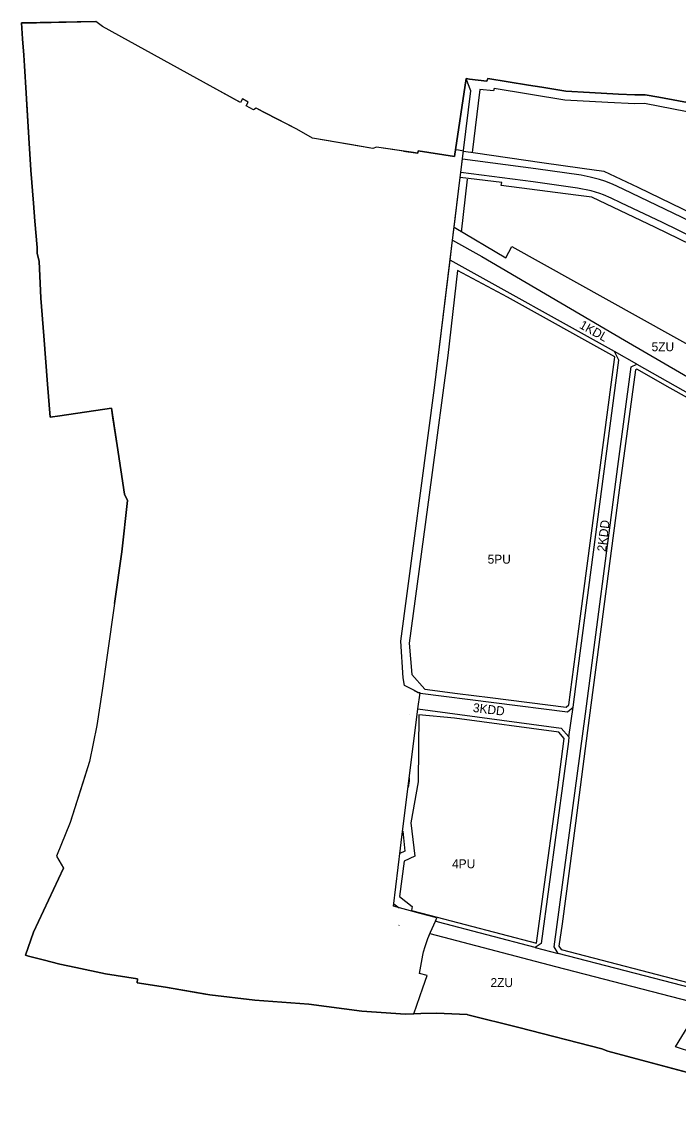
# Model space of a CAD drawing. Extents: x 7428203 to 7432868, y 5542672 to 5545406.
# Drawn here: x 7428203 to 7428940, y 5544072 to 5545281 of the extents above; entities that cross this region are included whole.
import ezdxf

# ---------------------------------------------------------------- set-up
doc = ezdxf.new("R2010")
doc.units = 0
for name, color, linetype in [('__LEGENDA_RAMKA_LOGO_PODZIAŁKA', 7, 'Continuous'), ('_GRANICA_MIASTA', 7, 'Continuous'), ('granicaBulwary', 7, 'Continuous'), ('LIN_Granica Planu', 7, 'Continuous'), ('MPZP_uchwalone_nieobowiazujace jeszcze_SZRAF', 7, 'Continuous')]:
    doc.layers.add(name, color=color, linetype=linetype)

msp = doc.modelspace()

# ---------------------------------------------------------------- linework, layer by layer
at = {"layer": '__LEGENDA_RAMKA_LOGO_PODZIAŁKA'}
msp.add_lwpolyline([(7428955.8, 5545189.3), (7428917.9, 5545196.3), (7428902.5, 5545199), (7428891, 5545198.8), (7428872.5, 5545199.5), (7428840.3, 5545201.4), (7428813.7, 5545202.9), (7428786.7, 5545207.3), (7428771.7, 5545209.8), (7428726, 5545217.2), (7428725.1, 5545214.2), (7428705.6, 5545216.5), (7428701.7, 5545217.3), (7428688.7, 5545129.6), (7428648, 5545136.2), (7428647.7, 5545133.5), (7428631.6, 5545135.8), (7428601.2, 5545140.2), (7428597.2, 5545138.9), (7428571.9, 5545143.2), (7428529.6, 5545150.4), (7428512, 5545160.3), (7428466.3, 5545184), (7428463.5, 5545182.1), (7428455.3, 5545186.6), (7428457.6, 5545190.8), (7428451.2, 5545194.3), (7428448.8, 5545190.4), (7428447.5, 5545191), (7428294.1, 5545275.5), (7428286.7, 5545281), (7428203.4, 5545279.4), (7428204.6, 5545261.5), (7428205.8, 5545243.5), (7428206.5, 5545231.5), (7428208.6, 5545200.8), (7428209.3, 5545187.6), (7428210.7, 5545163.1), (7428211.4, 5545150.6), (7428213.9, 5545114.4), (7428216.8, 5545077.6), (7428218.4, 5545057.2), (7428221, 5545027.7), (7428221, 5545021.2), (7428223.2, 5545012.5), (7428224.8, 5544971.2), (7428228.2, 5544928.7), (7428232.4, 5544874.6), (7428235.6, 5544837.6), (7428304.2, 5544847.7), (7428305.8, 5544836.9), (7428310.5, 5544805.9), (7428318.6, 5544751.6), (7428322.1, 5544744.5), (7428315.9, 5544686.9), (7428307.7, 5544629), (7428299.4, 5544571.1), (7428293.6, 5544531.6), (7428287.9, 5544492.2), (7428283.7, 5544472), (7428279.5, 5544451.8), (7428257.9, 5544383.7), (7428242.6, 5544345.7), (7428250.4, 5544332.5), (7428216.7, 5544260.7), (7428207.8, 5544234.9), (7428211.2, 5544234), (7428227.7, 5544229.8), (7428246.3, 5544225), (7428264.2, 5544221.1), (7428297.3, 5544213.9), (7428333.2, 5544208.5), (7428332.9, 5544203.8), (7428364.6, 5544199.1), (7428414.4, 5544190.6), (7428464.8, 5544184.5), (7428525.4, 5544180), (7428584.7, 5544172.2), (7428633.8, 5544168.9), (7428651.2, 5544169.5), (7428668.5, 5544170), (7428702.8, 5544168.3), (7428703.7, 5544168.2), (7428760.8, 5544154), (7428854, 5544130), (7428860.8, 5544127.5), (7428976.6, 5544096.4)], dxfattribs=at)
at = {"layer": '_GRANICA_MIASTA'}
for p, q in [((7428204.6, 5545261.5), (7428203.4, 5545279.4)), ((7428205.8, 5545243.5), (7428204.6, 5545261.5)), ((7428206.5, 5545231.5), (7428205.8, 5545243.5)), ((7428208.6, 5545200.8), (7428206.5, 5545231.5)), ((7428688.7, 5545129.6), (7428701.7, 5545217.3)), ((7428701.7, 5545217.3), (7428705.6, 5545216.5)), ((7428705.6, 5545216.5), (7428725.1, 5545214.2)), ((7428725.1, 5545214.2), (7428726, 5545217.2)), ((7428726, 5545217.2), (7428771.7, 5545209.8)), ((7428209.3, 5545187.6), (7428208.6, 5545200.8)), ((7428771.7, 5545209.8), (7428786.7, 5545207.3)), ((7428786.7, 5545207.3), (7428813.7, 5545202.9)), ((7428813.7, 5545202.9), (7428840.3, 5545201.4)), ((7428840.3, 5545201.4), (7428872.5, 5545199.5)), ((7428872.5, 5545199.5), (7428891, 5545198.8)), ((7428891, 5545198.8), (7428902.5, 5545199)), ((7428902.5, 5545199), (7428917.9, 5545196.3)), ((7428210.7, 5545163.1), (7428209.3, 5545187.6)), ((7428917.9, 5545196.3), (7428955.8, 5545189.3)), ((7428211.4, 5545150.6), (7428210.7, 5545163.1)), ((7428213.9, 5545114.4), (7428211.4, 5545150.6)), ((7428631.6, 5545135.8), (7428647.7, 5545133.5)), ((7428647.7, 5545133.5), (7428648, 5545136.2)), ((7428648, 5545136.2), (7428688.7, 5545129.6)), ((7428216.8, 5545077.6), (7428213.9, 5545114.4)), ((7428741.7, 5545100.7), (7428695.1, 5545106.2)), ((7428741.1, 5545097.4), (7428741.7, 5545100.7)), ((7428824.9, 5545086.3), (7428741.1, 5545097.4)), ((7428842.9, 5545084.3), (7428824.9, 5545086.3)), ((7428914.2, 5545050.1), (7428842.9, 5545084.3)), ((7428218.4, 5545057.2), (7428216.8, 5545077.6)), ((7428221, 5545027.7), (7428218.4, 5545057.2)), ((7428688.4, 5545050.6), (7428746.3, 5545016.4)), ((7429194.4, 5544914.9), (7428914.2, 5545050.1)), ((7428221, 5545021.2), (7428221, 5545027.7)), ((7428223.2, 5545012.5), (7428221, 5545021.2)), ((7428746.3, 5545016.4), (7428753, 5545028.9)), ((7428753, 5545028.9), (7429178.2, 5544792.5)), ((7428224.8, 5544971.2), (7428223.2, 5545012.5)), ((7428228.2, 5544928.7), (7428224.8, 5544971.2)), ((7428232.4, 5544874.6), (7428228.2, 5544928.7)), ((7428893.2, 5544897.2), (7428868.1, 5544911.3)), ((7428235.6, 5544837.6), (7428232.4, 5544874.6)), ((7428305.8, 5544836.9), (7428304.2, 5544847.7)), ((7428310.5, 5544805.9), (7428305.8, 5544836.9)), ((7428318.6, 5544751.6), (7428310.5, 5544805.9)), ((7428322.1, 5544744.5), (7428318.6, 5544751.6)), ((7428315.9, 5544686.9), (7428322.1, 5544744.5)), ((7428307.7, 5544629), (7428315.9, 5544686.9)), ((7428647.7, 5544510.8), (7428808.3, 5544489.4)), ((7428817, 5544479.5), (7428821.7, 5544512.7)), ((7428808.3, 5544489.4), (7428817, 5544479.5)), ((7428816.5, 5544474.3), (7428811.8, 5544438.6)), ((7428817, 5544479.5), (7428816.5, 5544474.3)), ((7428811.8, 5544438.6), (7428785.8, 5544248)), ((7428216.7, 5544260.7), (7428250.4, 5544332.5)), ((7428670.9, 5544272), (7428667.3, 5544272.9)), ((7428779.1, 5544243.6), (7428670.9, 5544272)), ((7428207.8, 5544234.9), (7428216.7, 5544260.7)), ((7428785.8, 5544248), (7428779.1, 5544243.6)), ((7428211.2, 5544234), (7428207.8, 5544234.9)), ((7428227.7, 5544229.8), (7428211.2, 5544234)), ((7428779.1, 5544243.6), (7428805.1, 5544236.8)), ((7428246.3, 5544225), (7428227.7, 5544229.8)), ((7428264.2, 5544221.1), (7428246.3, 5544225)), ((7428297.3, 5544213.9), (7428264.2, 5544221.1)), ((7428333.2, 5544208.5), (7428297.3, 5544213.9)), ((7428332.9, 5544203.8), (7428333.2, 5544208.5)), ((7428364.6, 5544199.1), (7428332.9, 5544203.8)), ((7428414.4, 5544190.6), (7428364.6, 5544199.1)), ((7428464.8, 5544184.5), (7428414.4, 5544190.6)), ((7428525.4, 5544180), (7428464.8, 5544184.5)), ((7428584.7, 5544172.2), (7428525.4, 5544180)), ((7428633.8, 5544168.9), (7428584.7, 5544172.2)), ((7428651.2, 5544169.5), (7428633.8, 5544168.9)), ((7428668.5, 5544170), (7428651.2, 5544169.5)), ((7428702.8, 5544168.3), (7428668.5, 5544170)), ((7428703.7, 5544168.2), (7428702.8, 5544168.3)), ((7428760.8, 5544154), (7428703.7, 5544168.2)), ((7428854, 5544130), (7428760.8, 5544154)), ((7428860.8, 5544127.5), (7428854, 5544130)), ((7428976.6, 5544096.4), (7428860.8, 5544127.5))]:
    msp.add_line(p, q, dxfattribs=at)
for points in [[(7428203.4, 5545279.4), (7428220.2, 5545279.7), (7428286.7, 5545281)], [(7428631.1, 5544545.6), (7428631.1, 5544545.6), (7428628.6, 5544586.7), (7428666.4, 5544870.6), (7428695.1, 5545106.2), (7428695.8, 5545111.9), (7428697.6, 5545127.5), (7428698.9, 5545136.6), (7428707, 5545203.5), (7428703.8, 5545211.9), (7428701.7, 5545217.3)], [(7429066.8, 5545002.4), (7428878, 5545093.2), (7428866, 5545098.8), (7428857.2, 5545102.2), (7428851.3, 5545104), (7428841, 5545106.7), (7428830.8, 5545108.9), (7428779.9, 5545116), (7428697.6, 5545126.8)], [(7428698.8, 5545135.9), (7428712.4, 5545134), (7428786.7, 5545123.1), (7428832, 5545116.8), (7428856.2, 5545113.4), (7428894.3, 5545095.5), (7429080.9, 5545005.1), (7429141.7, 5545005.5), (7429132.6, 5544978), (7429206.7, 5544943), (7429220.3, 5544939.2), (7429256.7, 5544938.9), (7429264.5, 5544938.1), (7429416.3, 5544933.1), (7429628, 5544926.1), (7429629.2, 5544929.1)], [(7428958, 5545038.3), (7428922, 5545055.7), (7428875.2, 5545078), (7428864.3, 5545083.1), (7428855.8, 5545086.7), (7428851.8, 5545088.2), (7428842, 5545091.2), (7428826.7, 5545094.4), (7428776.9, 5545101.3), (7428695.8, 5545111.9)], [(7428686.6, 5545035.9), (7428719.4, 5545017.6), (7428879.2, 5544923.9), (7428986.5, 5544861.5)], [(7428650.1, 5544528.6), (7428815.4, 5544507.4), (7428821.7, 5544512.7), (7428827.8, 5544559), (7428873, 5544901.7), (7428868.1, 5544911.3), (7428683.9, 5545013.6)], [(7429198.7, 5544727.5), (7429176.5, 5544739.6), (7429181.3, 5544730.1), (7429139.1, 5544411.7), (7429106, 5544162.4), (7429099.1, 5544157.9), (7428955.3, 5544197.9), (7428805.1, 5544236.8), (7428800.4, 5544244.1), (7428835.5, 5544505.4), (7428871.9, 5544782.6), (7428887, 5544894.3), (7428893.2, 5544897.2), (7428979.2, 5544848.5), (7428994.8, 5544839.8), (7428990.6, 5544827.8), (7428982.9, 5544761.7), (7428979.2, 5544729.8), (7429033.8, 5544721.6), (7429045.3, 5544798.2), (7429047.7, 5544810.4), (7429085.5, 5544789.4), (7429155.8, 5544750.9), (7429176.5, 5544739.6)], [(7428304.2, 5544847.7), (7428246.4, 5544839.2), (7428235.6, 5544837.6)], [(7428641.8, 5544532.5), (7428641.8, 5544532.4)], [(7428643.5, 5544531.6), (7428649, 5544528.8)], [(7428638.8, 5544504.4), (7428638.8, 5544504.4)], [(7428638.1, 5544433.7), (7428638.1, 5544430.1), (7428636.8, 5544422.8)], [(7428630.7, 5544373.7), (7428632.9, 5544351.6), (7428627.6, 5544348.9)], [(7428620.6, 5544292.5), (7428626.8, 5544288.1)], [(7428626.6, 5544268.5), (7428626.5, 5544268.1)], [(7429068.9, 5544072.2), (7429060.2, 5544098.7), (7429018.6, 5544105.3), (7428936.7, 5544132.4), (7428960.8, 5544171.8), (7428964.1, 5544180.1), (7428802.2, 5544221.9), (7428661.3, 5544259)]]:
    msp.add_lwpolyline(points, dxfattribs=at)
at = {"layer": 'LIN_Granica Planu'}
msp.add_lwpolyline([(7428399.9, 5545217.3), (7428294.1, 5545275.5), (7428286.7, 5545281), (7428203.4, 5545279.4), (7428204.6, 5545261.5), (7428208.6, 5545200.8), (7428211.4, 5545150.6), (7428213.9, 5545114.4), (7428218.4, 5545057.2), (7428221, 5545027.7), (7428221, 5545021.2), (7428223.2, 5545012.5), (7428224.8, 5544971.2), (7428232.4, 5544874.6), (7428235.6, 5544837.6), (7428246.4, 5544839.2), (7428304.2, 5544847.7), (7428310.5, 5544805.9), (7428318.6, 5544751.6), (7428322.1, 5544744.5), (7428321.8, 5544741), (7428315.9, 5544686.9), (7428307.7, 5544629), (7428299.4, 5544571.1), (7428293.6, 5544531.6), (7428287.9, 5544492.2), (7428279.5, 5544451.8), (7428271.6, 5544426.9), (7428257.9, 5544383.7), (7428242.6, 5544345.7), (7428250.4, 5544332.5), (7428216.7, 5544260.7), (7428207.8, 5544234.9), (7428211.2, 5544234), (7428211.2, 5544234), (7428211.2, 5544234), (7428211.2, 5544234), (7428207.8, 5544234.9), (7428211.2, 5544234), (7428227.7, 5544229.8), (7428246.3, 5544225), (7428264.2, 5544221.1), (7428297.3, 5544213.9), (7428333.2, 5544208.5), (7428332.9, 5544203.8), (7428364.6, 5544199.1), (7428409.6, 5544191.4), (7428414.4, 5544190.6), (7428464.8, 5544184.5), (7428525.4, 5544180), (7428584.7, 5544172.2), (7428633.8, 5544168.9), (7428641, 5544169.2), (7428643.2, 5544169.2), (7428653.2, 5544198.2), (7428658, 5544212), (7428658, 5544212.1), (7428649.4, 5544214.4), (7428653.2, 5544234.8), (7428653.9, 5544238.7), (7428655.9, 5544244.6), (7428656.4, 5544245.7), (7428659, 5544253.7), (7428662, 5544260.7), (7428667.3, 5544272.9), (7428669, 5544276.7), (7428650.4, 5544281.8), (7428620.2, 5544289.9), (7428628.3, 5544354.7), (7428629.1, 5544361), (7428647.7, 5544510.8), (7428650.1, 5544528.8), (7428648.2, 5544528.7), (7428643.5, 5544531.6), (7428643, 5544531.9), (7428632.7, 5544537.1), (7428631.1, 5544545.6), (7428628.6, 5544586.7), (7428666.4, 5544870.6), (7428683.9, 5545013.6), (7428686.6, 5545035.9), (7428688.4, 5545050.6), (7428695.1, 5545106.2), (7428695.8, 5545111.9), (7428697.6, 5545126.8), (7428697.6, 5545127.5), (7428698.8, 5545135.8), (7428693.4, 5545136.7), (7428689.8, 5545137.2), (7428688.7, 5545129.6), (7428648, 5545136.2), (7428647.7, 5545133.5), (7428642.8, 5545134.2), (7428601.2, 5545140.2), (7428597.2, 5545138.9), (7428529.6, 5545150.4), (7428512, 5545160.3), (7428474.8, 5545179.6), (7428466.3, 5545184), (7428463.5, 5545182.1), (7428455.3, 5545186.6), (7428457.6, 5545190.8), (7428451.2, 5545194.3), (7428448.8, 5545190.4)], close=True, dxfattribs=at)
at = {"layer": 'MPZP_uchwalone_nieobowiazujace jeszcze_SZRAF'}
for p, q in [((7428703, 5545104.5), (7428696.2, 5545044.9)), ((7428868.5, 5544905.4), (7428748, 5544972.3)), ((7428830, 5544614.8), (7428868.1, 5544902.4)), ((7428868.1, 5544902.4), (7428868.5, 5544905.4)), ((7428817, 5544515.6), (7428830, 5544614.8)), ((7428692.2, 5544528.3), (7428728.7, 5544523.6)), ((7428728.7, 5544523.6), (7428813.9, 5544512.7)), ((7428813.9, 5544512.7), (7428817, 5544515.6)), ((7428805.8, 5544484.7), (7428688.7, 5544500.3)), ((7428804.6, 5544422.8), (7428811.8, 5544477.8)), ((7428811.8, 5544477.8), (7428805.8, 5544484.7)), ((7428787.1, 5544294.9), (7428804.6, 5544422.8)), ((7428780.8, 5544248.3), (7428787.1, 5544294.9)), ((7428660.9, 5544279.7), (7428780.8, 5544248.3))]:
    msp.add_line(p, q, dxfattribs=at)
for points in [[(7429616.6, 5544926.6), (7429647.5, 5545018.3), (7429649.4, 5545036.4), (7429583.9, 5545048.4), (7429433, 5545062.8), (7429282.5, 5545076), (7429087.4, 5545134.5), (7429047.9, 5545146.1), (7429048.7, 5545151.7), (7428964, 5545172.7), (7428964.8, 5545176.8), (7428901.7, 5545189), (7428890.9, 5545188.8), (7428860.6, 5545190.2), (7428812.6, 5545193), (7428733.2, 5545205.9), (7428732.5, 5545203.2), (7428717.2, 5545204.8), (7428708.7, 5545134.4)], [(7428748, 5544972.3), (7428692.3, 5545002), (7428681.2, 5544906.8), (7428663, 5544770.2), (7428638, 5544584.6), (7428640.9, 5544549.4), (7428655.4, 5544533), (7428692.2, 5544528.3)], [(7428688.7, 5544500.3), (7428648.8, 5544504.3), (7428648.1, 5544429.2), (7428639.8, 5544383.3), (7428644.2, 5544345.9), (7428632.3, 5544340.1), (7428627.2, 5544300.5), (7428641.2, 5544289.4), (7428640.6, 5544284.9), (7428660.9, 5544279.7)]]:
    msp.add_lwpolyline(points, dxfattribs=at)
msp.add_lwpolyline([(7428893, 5544891.6), (7428891.6, 5544890.9), (7428873.4, 5544756), (7428838, 5544486.5), (7428824.5, 5544383), (7428809.5, 5544270.1), (7428805.6, 5544245.2), (7428808.3, 5544241.2), (7428960.5, 5544201.6), (7429063.1, 5544173.6), (7429098.4, 5544163.3), (7429101.4, 5544165.3), (7429115.2, 5544269.1), (7429156.7, 5544584.5), (7429176.1, 5544729.3), (7429172.7, 5544736), (7429073.4, 5544790.5), (7428930.4, 5544870.4)], close=True, dxfattribs=at)

# ---------------------------------------------------------------- texts
at = {"layer": 'granicaBulwary'}
for s, rotation, p in [('1KDL', 330.8924, (7428827.9, 5544938.1)), ('2KDD', 83.0729, (7428858.5, 5544686.5)), ('3KDD', 353.0729, (7428709, 5544507.5))]:
    msp.add_text(s, height=10, rotation=rotation, dxfattribs=at).set_placement(p)
for s, p in [('5ZU', (7428909.7, 5544911.6)), ('5PU', (7428725.9, 5544673.6)), ('4PU', (7428686, 5544332.3)), ('2ZU', (7428729.1, 5544199.2))]:
    msp.add_text(s, height=10, dxfattribs=at).set_placement(p)

doc.saveas('drawing.dxf')
